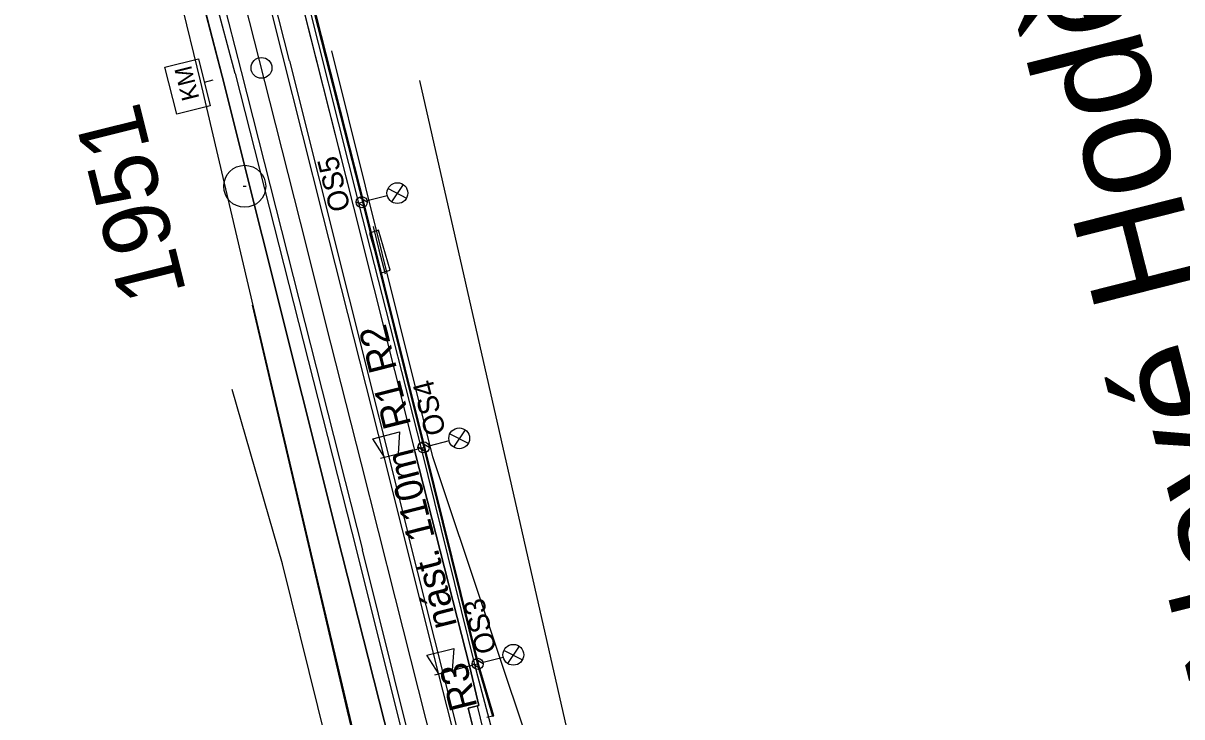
# Model space of a CAD drawing. Extents: x -754679 to -754173, y -1169241 to -1168288.
# Drawn here: x -754425.1 to -754341.7, y -1168914.1 to -1168864.2 of the extents above; entities that cross this region are included whole.
import ezdxf

# ---------------------------------------------------------------- set-up
doc = ezdxf.new("R2010")
doc.units = 0
for name, color, linetype in [('Vrstva 1', 7, 'Continuous'), ('Vrstva 14', 7, 'Continuous'), ('Vrstva 16', 7, 'Continuous'), ('Vrstva 2', 7, 'Continuous'), ('Vrstva 23', 7, 'Continuous'), ('Vrstva 25', 7, 'Continuous'), ('Vrstva 31', 7, 'Continuous'), ('Vrstva 33', 7, 'Continuous'), ('Vrstva 4', 7, 'Continuous'), ('Vrstva 43', 7, 'Continuous'), ('Vrstva 51', 7, 'Continuous'), ('Vrstva 53', 7, 'Continuous'), ('Vrstva 63', 7, 'Continuous'), ('Vrstva 7', 7, 'Continuous')]:
    doc.layers.add(name, color=color, linetype=linetype)

msp = doc.modelspace()

# ---------------------------------------------------------------- linework, layer by layer
at = {"layer": 'Vrstva 1'}
msp.add_line((-754409.148, -1168875.914), (-754409.148, -1168875.914), dxfattribs=at)
for points in [[(-754398.294, -1168905.574), (-754400.74, -1168895.891), (-754402.939, -1168887.198), (-754405.133, -1168878.507), (-754407.339, -1168869.778), (-754409.539, -1168861.07), (-754411.979, -1168851.401), (-754414.173, -1168842.726), (-754415.893, -1168835.935), (-754418.063, -1168827.345), (-754420.434, -1168817.966), (-754422.091, -1168811.412)], [(-754384.656, -1168959.571), (-754385.936, -1168954.491), (-754386.734, -1168951.322), (-754387.865, -1168946.893), (-754387.928, -1168946.598), (-754389.016, -1168942.293), (-754391.2, -1168933.67), (-754393.647, -1168923.979), (-754396.084, -1168914.315), (-754398.294, -1168905.574)]]:
    msp.add_lwpolyline(points, dxfattribs=at)
at = {"layer": 'Vrstva 14'}
for p, q in [((-754405.698, -1168860.083), (-754401.304, -1168877.422)), ((-754401.304, -1168877.422), (-754396.888, -1168895.004)), ((-754392.927, -1168910.532), (-754396.888, -1168895.004)), ((-754392.287, -1168913.272), (-754392.927, -1168910.532)), ((-754393.063, -1168913.475), (-754392.287, -1168913.272)), ((-754391.113, -1168921.242), (-754393.063, -1168913.475))]:
    msp.add_line(p, q, dxfattribs=at)
msp.add_lwpolyline([(-754414.276, -1168835.483), (-754412.566, -1168842.248), (-754407.917, -1168860.63), (-754403.513, -1168878.067), (-754399.115, -1168895.474), (-754395.207, -1168910.943), (-754391.772, -1168924.511), (-754387.375, -1168941.909)], dxfattribs=at)
at = {"layer": 'Vrstva 16'}
for p, q in [((-754412.329, -1168868.322), (-754417.897, -1168845.451)), ((-754410.781, -1168867.993), (-754402.14, -1168902.474)), ((-754404.14, -1168903.209), (-754412.329, -1168868.322)), ((-754402.14, -1168902.474), (-754395.222, -1168929.578)), ((-754397.82, -1168929.888), (-754404.14, -1168903.209))]:
    msp.add_line(p, q, dxfattribs=at)
msp.add_lwpolyline([(-754410.781, -1168867.993), (-754417.976, -1168840.388), (-754421.932, -1168825.961), (-754423.457, -1168821.011)], dxfattribs=at)
at = {"layer": 'Vrstva 23'}
for points in [[(-754381.681, -1168939.489), (-754386.122, -1168924.006), (-754387.953, -1168918.303), (-754395.607, -1168895.383), (-754402.869, -1168866.173)], [(-754399.909, -1168878.817), (-754399.485, -1168880.491), (-754399.03, -1168882.21)], [(-754393.344, -1168948.888), (-754397.546, -1168931.205), (-754401.742, -1168913.695), (-754408.583, -1168884.482)]]:
    msp.add_lwpolyline(points, dxfattribs=at)
msp.add_lwpolyline([(-754399.526, -1168879.083), (-754400.173, -1168879.277), (-754399.312, -1168882.147), (-754398.665, -1168881.952)], close=True, dxfattribs=at)
at = {"layer": 'Vrstva 25'}
for p, q in [((-754398.824, -1168876.083), (-754397.496, -1168876.762)), ((-754397.732, -1168875.791), (-754398.566, -1168877.027)), ((-754401.115, -1168877.031), (-754400.508, -1168877.393)), ((-754400.893, -1168876.698), (-754400.323, -1168877.038)), ((-754398.878, -1168876.59), (-754400.332, -1168876.958)), ((-754394.373, -1168893.733), (-754393.045, -1168894.412)), ((-754393.281, -1168893.442), (-754394.115, -1168894.678)), ((-754396.664, -1168894.682), (-754396.057, -1168895.044)), ((-754396.442, -1168894.349), (-754395.872, -1168894.689)), ((-754394.427, -1168894.241), (-754395.881, -1168894.609)), ((-754389.382, -1168909.02), (-754390.216, -1168910.256)), ((-754390.528, -1168909.819), (-754391.982, -1168910.187)), ((-754390.474, -1168909.312), (-754389.146, -1168909.991)), ((-754392.765, -1168910.26), (-754392.158, -1168910.622)), ((-754392.543, -1168909.927), (-754391.973, -1168910.267))]:
    msp.add_line(p, q, dxfattribs=at)
for points in [[(-754405.311, -1168859.885), (-754400.951, -1168877.139), (-754400.72, -1168877.056)], [(-754400.951, -1168877.139), (-754396.452, -1168894.774), (-754396.269, -1168894.707)], [(-754396.452, -1168894.774), (-754392.606, -1168910.34), (-754392.37, -1168910.285)], [(-754392.606, -1168910.34), (-754389.7, -1168921.276), (-754388.719, -1168923.201), (-754389.035, -1168923.735)]]:
    msp.add_lwpolyline(points, dxfattribs=at)
for centre, radius in [((-754398.153, -1168876.404), 0.749), ((-754400.72, -1168877.056), 0.4), ((-754393.702, -1168894.055), 0.749), ((-754396.269, -1168894.707), 0.4), ((-754389.803, -1168909.633), 0.749), ((-754392.37, -1168910.285), 0.4)]:
    msp.add_circle(centre, radius, dxfattribs=at)
at = {"layer": 'Vrstva 31'}
for points in [[(-754396.269, -1168894.707), (-754396.452, -1168894.774), (-754392.606, -1168910.34), (-754392.37, -1168910.285)], [(-754392.606, -1168910.34), (-754389.7, -1168921.276), (-754388.719, -1168923.201), (-754389.035, -1168923.735)]]:
    msp.add_lwpolyline(points, dxfattribs=at)
at = {"layer": 'Vrstva 33'}
for p, q in [((-754399.367, -1168895.491), (-754396.657, -1168894.805)), ((-754396.068, -1168895.052), (-754396.666, -1168894.696)), ((-754395.871, -1168894.704), (-754396.456, -1168894.355)), ((-754395.469, -1168911.068), (-754392.758, -1168910.383)), ((-754392.169, -1168910.63), (-754392.767, -1168910.274)), ((-754391.972, -1168910.282), (-754392.557, -1168909.933))]:
    msp.add_line(p, q, dxfattribs=at)
for points in [[(-754399.077, -1168895.417), (-754399.929, -1168894.086), (-754397.99, -1168893.595), (-754398.107, -1168895.172)], [(-754395.178, -1168910.995), (-754396.03, -1168909.663), (-754394.091, -1168909.173), (-754394.208, -1168910.75)]]:
    msp.add_lwpolyline(points, dxfattribs=at)
for centre in [(-754396.269, -1168894.707), (-754392.37, -1168910.285)]:
    msp.add_circle(centre, 0.401, dxfattribs=at)
at = {"layer": 'Vrstva 4'}
for p, q in [((-754409.837, -1168867.801), (-754424.763, -1168812.141)), ((-754423.571, -1168811.713), (-754409.415, -1168867.665)), ((-754425.102, -1168812.48), (-754410.781, -1168867.993)), ((-754405.916, -1168866.884), (-754414.18, -1168834.25)), ((-754405.916, -1168866.884), (-754397.327, -1168901.139)), ((-754402.14, -1168902.474), (-754410.781, -1168867.993)), ((-754409.837, -1168867.801), (-754401.081, -1168902.211)), ((-754409.415, -1168867.665), (-754400.667, -1168902.072)), ((-754390.328, -1168928.8), (-754397.327, -1168901.139)), ((-754401.081, -1168902.211), (-754394.179, -1168929.708)), ((-754393.809, -1168929.698), (-754400.667, -1168902.072)), ((-754395.222, -1168929.578), (-754402.14, -1168902.474))]:
    msp.add_line(p, q, dxfattribs=at)
at = {"layer": 'Vrstva 43'}
msp.add_line((-754392.405, -1168913.302), (-754391.226, -1168918.175), dxfattribs=at)
at = {"layer": 'Vrstva 51'}
for p, q in [((-754405.058, -1168859.927), (-754400.625, -1168877.238)), ((-754400.518, -1168877.236), (-754404.921, -1168859.923)), ((-754400.625, -1168877.238), (-754396.226, -1168894.847)), ((-754396.119, -1168894.852), (-754400.518, -1168877.236)), ((-754396.226, -1168894.847), (-754392.355, -1168910.448)), ((-754392.262, -1168910.44), (-754396.119, -1168894.852)), ((-754392.355, -1168910.448), (-754391.3, -1168914.039)), ((-754391.199, -1168914.018), (-754392.262, -1168910.44)), ((-754391.3, -1168914.039), (-754391.701, -1168914.153)), ((-754391.3, -1168914.039), (-754391.199, -1168914.018))]:
    msp.add_line(p, q, dxfattribs=at)
msp.add_lwpolyline([(-754412.047, -1168834.907), (-754410.208, -1168842.187), (-754405.698, -1168860.083), (-754401.304, -1168877.422), (-754396.888, -1168895.004), (-754392.927, -1168910.532), (-754392.287, -1168913.272), (-754393.063, -1168913.475), (-754391.113, -1168921.242), (-754390.299, -1168921.015), (-754389.528, -1168924.038), (-754385.162, -1168941.315)], dxfattribs=at)
at = {"layer": 'Vrstva 53'}
for p, q in [((-754396.56, -1168868.29), (-754379.05, -1168945.33)), ((-754406.43, -1168903.09), (-754410.06, -1168890.53)), ((-754396.05, -1168944.82), (-754406.43, -1168903.09))]:
    msp.add_line(p, q, dxfattribs=at)
at = {"layer": 'Vrstva 63'}
msp.add_line((-754409.248, -1168875.914), (-754409.048, -1168875.914), dxfattribs=at)
msp.add_circle((-754409.148, -1168875.914), 1.512, dxfattribs=at)
at = {"layer": 'Vrstva 7'}
msp.add_line((-754411.454, -1168868.282), (-754412.058, -1168868.435), dxfattribs=at)
msp.add_lwpolyline([(-754411.631, -1168870.124), (-754414.039, -1168870.732), (-754414.893, -1168867.35), (-754412.486, -1168866.742)], close=True, dxfattribs=at)
msp.add_circle((-754407.941, -1168867.395), 0.75, dxfattribs=at)

# ---------------------------------------------------------------- texts
at = {"layer": 'Vrstva 14'}
msp.add_text('nást. 110m', height=2, rotation=104.17821, dxfattribs=at).set_placement((-754393.844, -1168907.498))
at = {"layer": 'Vrstva 2'}
msp.add_text('1951', height=4.8, rotation=104.00179, dxfattribs=at).set_placement((-754413.336, -1168883.555))
at = {"layer": 'Vrstva 23'}
msp.add_text('zast. Nové Hodějovice', height=8, rotation=104.17859, dxfattribs=at).set_placement((-754326.915, -1168935.19))
at = {"layer": 'Vrstva 25'}
for s, rotation, p in [('OS5', 104.16802, (-754401.518, -1168877.525)), ('OS4', 104.17678, (-754394.646, -1168893.635)), ('OS3', 104.18883, (-754390.989, -1168909.35))]:
    msp.add_text(s, height=1.5, rotation=rotation, dxfattribs=at).set_placement(p)
at = {"layer": 'Vrstva 33'}
for s, rotation, p in [('R1 R2', 104.19587, (-754397.154, -1168893.084)), ('R3', 104.18883, (-754392.378, -1168913.363))]:
    msp.add_text(s, height=2, rotation=rotation, dxfattribs=at).set_placement(p)
at = {"layer": 'Vrstva 7'}
msp.add_text('KM', height=1.2469, rotation=104.17859, dxfattribs=at).set_placement((-754412.409, -1168869.572))

doc.saveas('drawing.dxf')
